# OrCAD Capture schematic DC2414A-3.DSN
size Custom; title: LTC626X  TRANSIMPEDANCE AMPLIFIER; rev: 3; company: TM
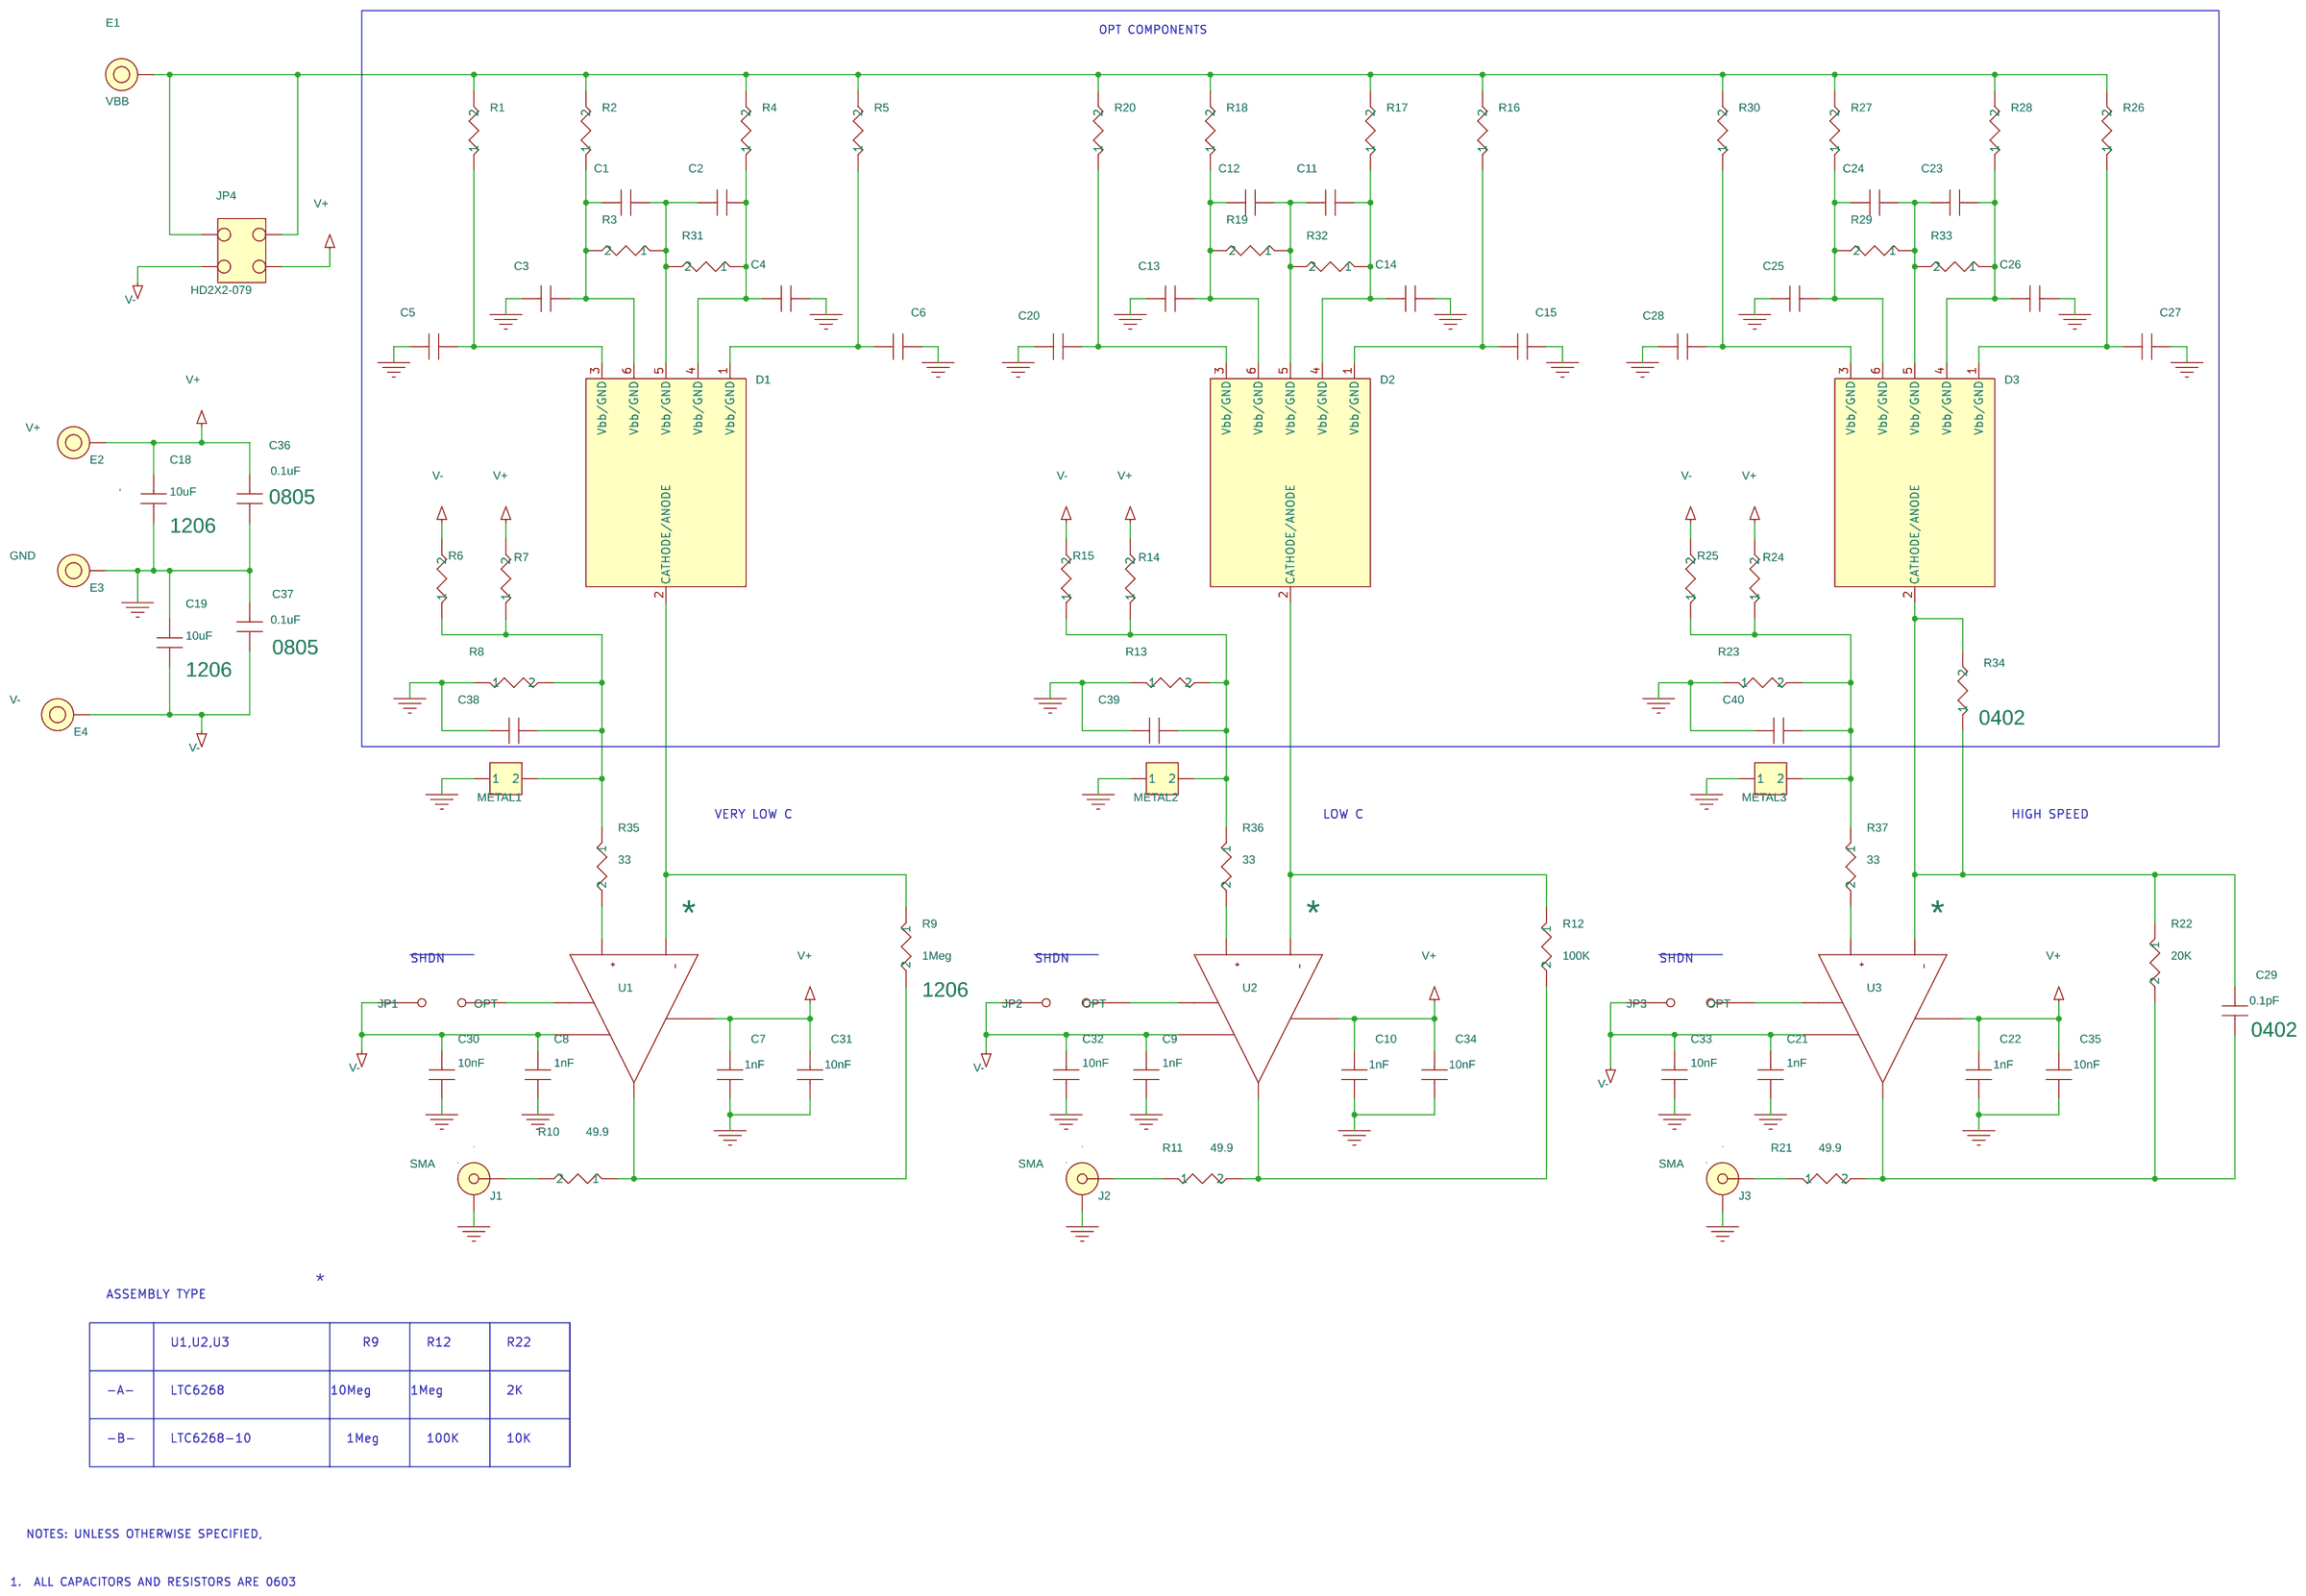
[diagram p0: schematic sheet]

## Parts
C1  OPT  [0603]
C2  OPT  [0603]
C3  OPT  [0603]
C4  OPT  [0603]
C5  OPT  [0603]
C6  OPT  [0603]
C7  1nF  [0603]
C8  1nF  [0603]
C9  1nF  [0603]
C10  1nF  [0603]
C11  OPT  [0603]
C12  OPT  [0603]
C13  OPT  [0603]
C14  OPT  [0603]
C15  OPT  [0603]
C18  10uF  [1206-ALL-SIZE-CAP]
C19  10uF  [1206-ALL-SIZE-CAP]
C20  OPT  [0603]
C21  1nF  [0603]
C22  1nF  [0603]
C23  OPT  [0603]
C24  OPT  [0603]
C25  OPT  [0603]
C26  OPT  [0603]
C27  OPT  [0603]
C28  OPT  [0603]
C29  0.1pF  [0402]
C30  10nF  [0603]
C31  10nF  [0603]
C32  10nF  [0603]
C33  10nF  [0603]
C34  10nF  [0603]
C35  10nF  [0603]
C36  0.1uF  [0805]
C37  0.1uF  [0805]
C38  OPT  [0603]
C39  OPT  [0603]
C40  OPT  [0603]
D1  OPT  [6PIN-DIODE-EDGE]
D2  OPT  [6PIN-DIODE-EDGE]
D3  OPT  [6PIN-DIODE-EDGE]
E1  VBB  [MILLMAX2501]
E2  V+  [MILLMAX2501]
E3  GND  [MILLMAX2501]
E4  V-  [MILLMAX2501]
J1  SMA  [CON\SMA-END-GLEN]
J2  SMA  [CON\SMA-END-GLEN]
J3  SMA  [CON\SMA-END-GLEN]
JP1  OPT  [HD1X2-079]
JP2  OPT  [HD1X2-079]
JP3  OPT  [HD1X2-079]
JP4  HD2X2-079  [HDR\2X2\079]
METAL1  TBD  [CUT]
METAL2  TBD  [CUT]
METAL3  TBD  [CUT]
R1  OPT  [0603]
R2  OPT  [0603]
R3  OPT  [0603]
R4  OPT  [0603]
R5  OPT  [0603]
R6  OPT  [0603]
R7  OPT  [0603]
R8  OPT  [0603]
R9  1Meg  [1206]
R10  49.9  [0603]
R11  49.9  [0603]
R12  100K  [0603]
R13  OPT  [0603]
R14  OPT  [0603]
R15  OPT  [0603]
R16  OPT  [0603]
R17  OPT  [0603]
R18  OPT  [0603]
R19  OPT  [0603]
R20  OPT  [0603]
R21  49.9  [0603]
R22  20K  [0603]
R23  OPT  [0603]
R24  OPT  [0603]
R25  OPT  [0603]
R26  OPT  [0603]
R27  OPT  [0603]
R28  OPT  [0603]
R29  OPT  [0603]
R30  OPT  [0603]
R31  OPT  [0603]
R32  OPT  [0603]
R33  OPT  [0603]
R34  OPT  [0402]
R35  33  [0603]
R36  33  [0603]
R37  33  [0603]
U1  *  [TSOT-23-6]
U2  *  [TSOT-23-6]
U3  *  [TSOT-23-6]

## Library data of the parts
C1-C15 C20-C40 = 1.0uF_10V_10%_X5R_0603
C18 C19 = 1.0uF_10V_10%_X5R_0603: Package: 1206
D1-D3 = PHOTODIODE_13
E1-E4 = TURRETL_4: TURRET; 1: 5V-40V; Part Number: MILL MAX 2501
J1-J3 = CON_SMA-END_3
JP1-JP3 = JUMPER,_2_PIN_.079
JP4 = HEADER_2X2_.079
METAL1 = R_0_2: RES, 0603 4.99K OHMS  1% 1/10W; 5%: 1%; Part Number: NIC NRC06F4991TRF; Tol: 1%
METAL2 = R_0_1: RES, 0603 4.99K OHMS  1% 1/10W; 5%: 1%; Part Number: NIC NRC06F4991TRF; Tol: 1%
METAL3 = R_0: RES, 0603 4.99K OHMS  1% 1/10W; 5%: 1%; Part Number: NIC NRC06F4991TRF; Tol: 1%
R1 = R_29: RES, 0603 4.99K OHMS  1% 1/10W; 5%: 1%; Part Number: NIC NRC06F4991TRF; Tol: 1%
R2 = R_25: RES, 0603 4.99K OHMS  1% 1/10W; 5%: 1%; Part Number: NIC NRC06F4991TRF; Tol: 1%
R3 = R_9: RES, 0603 4.99K OHMS  1% 1/10W; 5%: 1%; Part Number: NIC NRC06F4991TRF; Tol: 1%
R4 = R_7: RES, 0603 4.99K OHMS  1% 1/10W; 5%: 1%; Part Number: NIC NRC06F4991TRF; Tol: 1%
R5 = R_26: RES, 0603 4.99K OHMS  1% 1/10W; 5%: 1%; Part Number: NIC NRC06F4991TRF; Tol: 1%
R6 = R_23: RES, 0603 4.99K OHMS  1% 1/10W; 5%: 1%; Part Number: NIC NRC06F4991TRF; Tol: 1%
R7 = R_10: RES, 0603 4.99K OHMS  1% 1/10W; 5%: 1%; Part Number: NIC NRC06F4991TRF; Tol: 1%
R8 = R_35: RES, 0603 4.99K OHMS  1% 1/10W; 5%: 1%; Part Number: NIC NRC06F4991TRF; Tol: 1%
R9 = R_32: RES, 0603 4.99K OHMS  1% 1/10W; 5%: 1%; Part Number: NIC NRC06F4991TRF; Tol: 1%
R10 = R_13: RES, 0603 4.99K OHMS  1% 1/10W; 5%: 1%; Part Number: NIC NRC06F4991TRF; Tol: 1%
R11 = R_27: RES, 0603 4.99K OHMS  1% 1/10W; 5%: 1%; Part Number: NIC NRC06F4991TRF; Tol: 1%
R12 = R_8: RES, 0603 4.99K OHMS  1% 1/10W; 5%: 1%; Part Number: NIC NRC06F4991TRF; Tol: 1%
R13 = R_30: RES, 0603 4.99K OHMS  1% 1/10W; 5%: 1%; Part Number: NIC NRC06F4991TRF; Tol: 1%
R14 = R_31: RES, 0603 4.99K OHMS  1% 1/10W; 5%: 1%; Part Number: NIC NRC06F4991TRF; Tol: 1%
R15 = R_14: RES, 0603 4.99K OHMS  1% 1/10W; 5%: 1%; Part Number: NIC NRC06F4991TRF; Tol: 1%
R16 = R_16: RES, 0603 4.99K OHMS  1% 1/10W; 5%: 1%; Part Number: NIC NRC06F4991TRF; Tol: 1%
R17 = R_36: RES, 0603 4.99K OHMS  1% 1/10W; 5%: 1%; Part Number: NIC NRC06F4991TRF; Tol: 1%
R18 = R_20: RES, 0603 4.99K OHMS  1% 1/10W; 5%: 1%; Part Number: NIC NRC06F4991TRF; Tol: 1%
R19 = R_4: RES, 0603 4.99K OHMS  1% 1/10W; 5%: 1%; Part Number: NIC NRC06F4991TRF; Tol: 1%
R20 = R_22: RES, 0603 4.99K OHMS  1% 1/10W; 5%: 1%; Part Number: NIC NRC06F4991TRF; Tol: 1%
R21 = R_1: RES, 0603 4.99K OHMS  1% 1/10W; 5%: 1%; Part Number: NIC NRC06F4991TRF; Tol: 1%
R22 = R_34: RES, 0603 4.99K OHMS  1% 1/10W; 5%: 1%; Part Number: NIC NRC06F4991TRF; Tol: 1%
R23 = R_11: RES, 0603 4.99K OHMS  1% 1/10W; 5%: 1%; Part Number: NIC NRC06F4991TRF; Tol: 1%
R24 = R_2: RES, 0603 4.99K OHMS  1% 1/10W; 5%: 1%; Part Number: NIC NRC06F4991TRF; Tol: 1%
R25 = R_18: RES, 0603 4.99K OHMS  1% 1/10W; 5%: 1%; Part Number: NIC NRC06F4991TRF; Tol: 1%
R26 = R: RES, 0603 4.99K OHMS  1% 1/10W; 5%: 1%; Part Number: NIC NRC06F4991TRF; Tol: 1%
R27 = R_3: RES, 0603 4.99K OHMS  1% 1/10W; 5%: 1%; Part Number: NIC NRC06F4991TRF; Tol: 1%
R28 = R_21: RES, 0603 4.99K OHMS  1% 1/10W; 5%: 1%; Part Number: NIC NRC06F4991TRF; Tol: 1%
R29 = R_6: RES, 0603 4.99K OHMS  1% 1/10W; 5%: 1%; Part Number: NIC NRC06F4991TRF; Tol: 1%
R30 = R_15: RES, 0603 4.99K OHMS  1% 1/10W; 5%: 1%; Part Number: NIC NRC06F4991TRF; Tol: 1%
R31 = R_5: RES, 0603 4.99K OHMS  1% 1/10W; 5%: 1%; Part Number: NIC NRC06F4991TRF; Tol: 1%
R32 = R_24: RES, 0603 4.99K OHMS  1% 1/10W; 5%: 1%; Part Number: NIC NRC06F4991TRF; Tol: 1%
R33 = R_12: RES, 0603 4.99K OHMS  1% 1/10W; 5%: 1%; Part Number: NIC NRC06F4991TRF; Tol: 1%
R34 = R_19: RES, 0603 4.99K OHMS  1% 1/10W; 5%: 1%; Part Number: NIC NRC06F4991TRF; Tol: 1%
R35 = R_17: RES, 0603 4.99K OHMS  1% 1/10W; 5%: 1%; Part Number: NIC NRC06F4991TRF; Tol: 1%
R36 = R_28: RES, 0603 4.99K OHMS  1% 1/10W; 5%: 1%; Part Number: NIC NRC06F4991TRF; Tol: 1%
R37 = R_33: RES, 0603 4.99K OHMS  1% 1/10W; 5%: 1%; Part Number: NIC NRC06F4991TRF; Tol: 1%
U1-U3 = LTC6268_2

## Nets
GND: C3.1 C4.2 C5.1 C6.1 C7.2 C8.2 C9.2 C10.2 C13.1 C14.2 C15.1 C18.1 C19.2 C20.2 C21.2 C22.2 C25.1 C26.2 C27.1 C28.2 C30.2 C31.2 C32.2 C33.2 C34.2 C35.2 C36.1 C37.2 C38.1 C39.1 C40.1 E3.1(TP) J1.2(GND) J1.3(GND) J1.4(GND) J1.5(GND) J2.2(GND) J2.3(GND) J2.4(GND) J2.5(GND) J3.2(GND) J3.3(GND) J3.4(GND) J3.5(GND) METAL1.1 METAL2.1 METAL3.1 R8.1 R13.1 R23.1
V+: C7.1 C10.1 C18.2 C22.1 C31.1 C34.1 C35.1 C36.2 E2.1(TP) JP4.4 R7.2 R14.2 R24.2 U1.6 U2.6 U3.6
V-: C8.1 C9.1 C19.1 C21.1 C30.1 C32.1 C33.1 C37.1 E4.1(TP) JP1.1 JP2.1 JP3.1 JP4.3 R6.2 R15.2 R25.2 U1.2 U2.2 U3.2
N27405199: C6.2 D1.1(Vbb/GND) R5.1
N27405247: C38.2 METAL1.2 R6.1 R7.1 R8.2 R35.1
N27405283: JP1.2 U1.5
N27405411: D1.2(CATHODE/ANODE) R9.1 U1.4
N27405413: R9.2 R10.1 U1.1
N27405505: C2.2 C4.1 D1.4(Vbb/GND) R4.1 R31.1
N27405524: C1.1 C3.2 D1.6(Vbb/GND) R2.1 R3.2
N27405563: C5.2 D1.3(Vbb/GND) R1.1
N27405653: E1.1(TP) JP4.1 JP4.2 R1.2 R2.2 R4.2 R5.2 R16.2 R17.2 R18.2 R20.2 R26.2 R27.2 R28.2 R30.2
N27407291: C1.2 C2.1 D1.5(Vbb/GND) R3.1 R31.2
N27410916: C15.2 D2.1(Vbb/GND) R16.1
N27410939: C39.2 METAL2.2 R13.2 R14.1 R15.1 R36.1
N27411028: D2.2(CATHODE/ANODE) R12.1 U2.4
N27411030: R11.2 R12.2 U2.1
N27411105: JP2.2 U2.5
N27411112: C11.2 C14.1 D2.4(Vbb/GND) R17.1 R32.1
N27411131: C12.1 C13.2 D2.6(Vbb/GND) R18.1 R19.2
N27411160: C20.1 D2.3(Vbb/GND) R20.1
N27411196: C11.1 C12.2 D2.5(Vbb/GND) R19.1 R32.2
N27416785: C27.2 D3.1(Vbb/GND) R26.1
N27416797: C40.2 METAL3.2 R23.2 R24.1 R25.1 R37.1
N27416881: C29.1 D3.2(CATHODE/ANODE) R22.1 R34.1 R34.2 U3.4
N27416883: C29.2 R21.2 R22.2 U3.1
N27416955: JP3.2 U3.5
N27416957: C23.2 C26.1 D3.4(Vbb/GND) R28.1 R33.1
N27416971: C24.1 C25.2 D3.6(Vbb/GND) R27.1 R29.2
N27417001: C28.1 D3.3(Vbb/GND) R30.1
N27417037: C23.1 C24.2 D3.5(Vbb/GND) R29.1 R33.2
N27442273: J1.1(CENTER) R10.2
N27443850: J2.1(CENTER) R11.1
N27445097: J3.1(CENTER) R21.1
N27454612: R37.2 U3.3
N27454659: R36.2 U2.3
N27454721: R35.2 U1.3

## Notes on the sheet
- OPT COMPONENTS
- VERY LOW C
- LOW C
- HIGH SPEED
- SHDN
- SHDN
- SHDN
- *
- ASSEMBLY TYPE
- U1,U2,U3
- R9
- R12
- R22
- -A-
- LTC6268
- 10Meg
- 1Meg
- 2K
- -B-
- LTC6268-10
- 1Meg
- 100K
- 10K
- NOTES: UNLESS OTHERWISE SPECIFIED,
- 1.  ALL CAPACITORS AND RESISTORS ARE 0603
